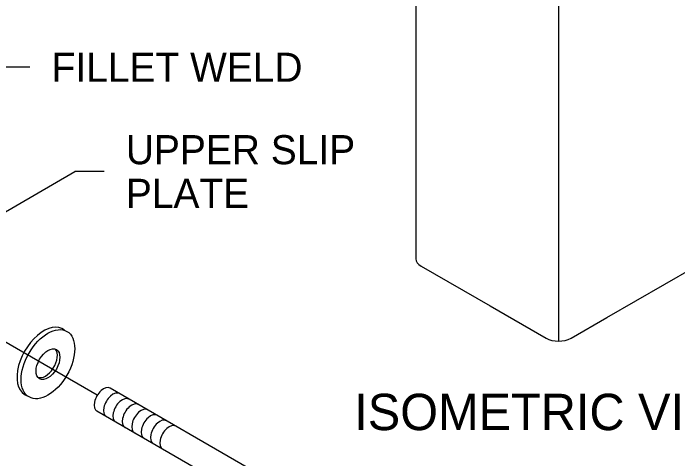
# Model space of a CAD drawing. Extents: x 99862 to 103151, y 99997 to 117076.
# Drawn here: x 101336 to 101701.2, y 103787.3 to 104032.1 of the extents above; entities that cross this region are included whole.
import ezdxf

# ---------------------------------------------------------------- set-up
doc = ezdxf.new("R2010")
doc.units = 0
for name, color, linetype in [('Level 13', 7, 'Continuous'), ('Level 15', 7, 'Continuous'), ('Level 20', 7, 'Continuous'), ('Level 4', 7, 'Continuous')]:
    doc.layers.add(name, color=color, linetype=linetype)

msp = doc.modelspace()

# ---------------------------------------------------------------- linework, layer by layer
at = {"layer": 'Level 13'}
for p, q in [((101480.05, 103773.61), (101389.27, 103826.02)), ((101472.36, 103761.23), (101381.99, 103813.4))]:
    msp.add_line(p, q, dxfattribs=at)
for centre, major_axis, start_param, end_param in [((101352.74, 103840.52), (-10.41, -18.04), 3.042453, 6.404476), ((101353.71, 103840.27), (-4.63, -8.02), 0.083455, 2.907882), ((101385.63, 103819.71), (3.64, 6.31), 6.283173, 9.424785), ((101390.79, 103816.74), (3.64, 6.31), 6.283174, 9.424783), ((101395.94, 103813.76), (3.64, 6.31), 6.283172, 9.424785), ((101401.09, 103810.78), (3.64, 6.31), 6.283179, 9.424784), ((101406.25, 103807.81), (3.64, 6.31), 6.283177, 9.424782), ((101411.4, 103804.83), (3.64, 6.31), 6.283174, 9.424785), ((101416.55, 103801.86), (3.64, 6.31), 6.283176, 9.424783), ((101421.71, 103798.88), (3.64, 6.31), 6.283178, 9.42478)]:
    msp.add_ellipse(centre, major_axis=major_axis, ratio=0.57735, start_param=start_param, end_param=end_param, dxfattribs=at)
for major_axis in [(-10.41, -18.04), (-4.63, -8.02)]:
    msp.add_ellipse((101355.06, 103839.24), major_axis=major_axis, ratio=0.57735, dxfattribs=at)
at = {"layer": 'Level 15'}
for p, q in [((101345.08, 104002.46), (101329.08, 104002.46)), ((101313.59, 103912.62), (101369.88, 103945.12)), ((101385.88, 103945.12), (101369.88, 103945.12)), ((101382.18, 103822.14), (101211.49, 103920.68))]:
    msp.add_line(p, q, dxfattribs=at)
at = {"layer": 'Level 4'}
for p, q in [((101635.72, 104123.92), (101635.72, 103851.89)), ((101557.33, 104111.37), (101557.33, 103897.15)), ((101662.23, 103864.87), (101711.26, 103893.18)), ((101598.14, 103871.27), (101628.85, 103853.54)), ((101642.59, 103853.54), (101662.23, 103864.87))]:
    msp.add_line(p, q, dxfattribs=at)
msp.add_lwpolyline([(101560.18, 103893.18), (101598.14, 103871.27)], dxfattribs=at)
for centre, major_axis, start_param, end_param in [((101567.04, 103897.15), (9.71, 0), 3.141593, 3.926991), ((101635.72, 103857.5), (-9.71, 0), 0.785398, 2.356194)]:
    msp.add_ellipse(centre, major_axis=major_axis, ratio=0.57735, start_param=start_param, end_param=end_param, dxfattribs=at)

# ---------------------------------------------------------------- texts
at = {"layer": 'Level 20'}
for s, height, p in [('FILLET WELD', 16, (101357.08, 103994.46)), ('UPPER SLIP', 16, (101397.88, 103949.13)), ('PLATE', 16, (101397.88, 103925.13)), ('ISOMETRIC VIEW', 20, (101523.42, 103802.98))]:
    msp.add_text(s, height=height, dxfattribs=at).set_placement(p)

doc.saveas('drawing.dxf')
